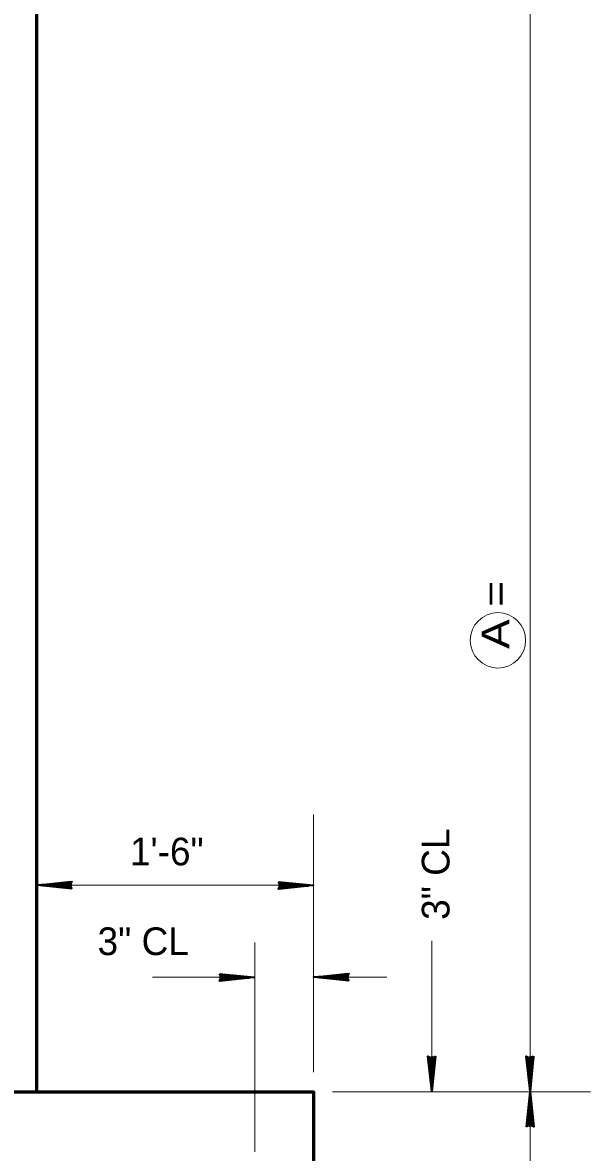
# Model space of a CAD drawing. Extents: x 6.34 to 9.53, y -1.46 to 0.53.
# Drawn here: x 7.298 to 7.4689, y -0.7412 to -0.4014 of the extents above; entities that cross this region are included whole.
import ezdxf

# ---------------------------------------------------------------- set-up
doc = ezdxf.new("R2010")
doc.units = 0
doc.header["$LTSCALE"] = 0.0033
doc.layers.add('1', color=7, linetype='Continuous', lineweight=40)

msp = doc.modelspace()

# ---------------------------------------------------------------- linework, layer by layer
at = {"layer": '1', "lineweight": 13}
for p, q in [((7.45075, -0.391417), (7.45075, -0.80625)), ((7.385583, -0.717), (7.385583, -0.639583)), ((7.30225, -0.660833), (7.385167, -0.660833)), ((7.367917, -0.741), (7.367917, -0.678083)), ((7.421167, -0.712917), (7.421167, -0.677583)), ((7.337083, -0.6885), (7.357917, -0.6885)), ((7.3955, -0.6885), (7.407667, -0.6885)), ((7.39125, -0.722917), (7.468917, -0.722917))]:
    msp.add_line(p, q, dxfattribs=at)
at = {"layer": '1', "lineweight": 35}
for p, q in [((7.312833, -0.660833), (7.30225, -0.660833)), ((7.312583, -0.661667), (7.30475, -0.660667)), ((7.312583, -0.661667), (7.30475, -0.660833)), ((7.312583, -0.661833), (7.30475, -0.660917)), ((7.312583, -0.661833), (7.30475, -0.660917)), ((7.312583, -0.66175), (7.30475, -0.660917)), ((7.312583, -0.65975), (7.30525, -0.660583)), ((7.312583, -0.659917), (7.30525, -0.660667)), ((7.312583, -0.66), (7.30525, -0.660833)), ((7.312667, -0.660167), (7.305333, -0.660917)), ((7.375, -0.660833), (7.385583, -0.660833)), ((7.375167, -0.6615), (7.3825, -0.66075)), ((7.37525, -0.659833), (7.383083, -0.66075)), ((7.37525, -0.659833), (7.383083, -0.66075)), ((7.37525, -0.659917), (7.383083, -0.66075)), ((7.37525, -0.66), (7.383083, -0.660833)), ((7.37525, -0.66), (7.383083, -0.661)), ((7.37525, -0.661667), (7.382583, -0.660833)), ((7.37525, -0.66175), (7.382583, -0.661)), ((7.37525, -0.661917), (7.382583, -0.661083)), ((7.35725, -0.6885), (7.367833, -0.6885)), ((7.357417, -0.689167), (7.36475, -0.688417)), ((7.3575, -0.6875), (7.365333, -0.688417)), ((7.3575, -0.6875), (7.365333, -0.688417)), ((7.3575, -0.687583), (7.365333, -0.688417)), ((7.3575, -0.687667), (7.365333, -0.6885)), ((7.3575, -0.687667), (7.365333, -0.688667)), ((7.3575, -0.689333), (7.364833, -0.6885)), ((7.3575, -0.689417), (7.364833, -0.688667)), ((7.3575, -0.689583), (7.364833, -0.68875)), ((7.396167, -0.6885), (7.385583, -0.6885)), ((7.395917, -0.689333), (7.388083, -0.688333)), ((7.395917, -0.689333), (7.388083, -0.6885)), ((7.395917, -0.6895), (7.388083, -0.688583)), ((7.395917, -0.6895), (7.388083, -0.688583)), ((7.395917, -0.689417), (7.388083, -0.688583)), ((7.395917, -0.687417), (7.388583, -0.68825)), ((7.395917, -0.687583), (7.388583, -0.688333)), ((7.395917, -0.687667), (7.388583, -0.6885)), ((7.396, -0.687833), (7.388667, -0.688583)), ((7.420083, -0.7125), (7.420917, -0.719833)), ((7.42025, -0.7125), (7.421, -0.719833)), ((7.420333, -0.7125), (7.421167, -0.719833)), ((7.4205, -0.712417), (7.42125, -0.71975)), ((7.422, -0.7125), (7.421, -0.720333)), ((7.421167, -0.71225), (7.421167, -0.722833)), ((7.422, -0.7125), (7.421167, -0.720333)), ((7.422167, -0.7125), (7.42125, -0.720333)), ((7.422167, -0.7125), (7.42125, -0.720333)), ((7.422083, -0.7125), (7.42125, -0.720333)), ((7.449667, -0.7125), (7.4505, -0.719833)), ((7.449833, -0.7125), (7.450583, -0.719833)), ((7.449917, -0.7125), (7.45075, -0.719833)), ((7.450083, -0.712417), (7.450833, -0.71975)), ((7.451583, -0.7125), (7.450583, -0.720333)), ((7.45075, -0.71225), (7.45075, -0.722833)), ((7.451583, -0.7125), (7.45075, -0.720333)), ((7.45175, -0.7125), (7.450833, -0.720333)), ((7.45175, -0.7125), (7.450833, -0.720333)), ((7.451667, -0.7125), (7.450833, -0.720333)), ((7.45075, -0.7335), (7.45075, -0.722917)), ((7.44975, -0.73325), (7.450667, -0.725417)), ((7.44975, -0.73325), (7.450667, -0.725417)), ((7.449833, -0.73325), (7.450667, -0.725417)), ((7.449917, -0.73325), (7.45075, -0.725417)), ((7.449917, -0.73325), (7.450917, -0.725417)), ((7.451417, -0.733333), (7.450667, -0.726)), ((7.451583, -0.73325), (7.45075, -0.725917)), ((7.451667, -0.73325), (7.450917, -0.725917)), ((7.451833, -0.73325), (7.451, -0.725917))]:
    msp.add_line(p, q, dxfattribs=at)
at = {"layer": '1', "lineweight": 60}
for points in [[(7.30225, -0.389583), (7.30225, -0.722917), (7.385583, -0.722917), (7.385583, -0.80625)], [(6.718917, -0.722917), (6.962083, -0.722917), (7.30225, -0.722917)]]:
    msp.add_lwpolyline(points, dxfattribs=at)
at = {"layer": '1', "lineweight": 35}
for points in [[(7.312833, -0.661917), (7.30225, -0.660833), (7.312833, -0.659667), (7.31225, -0.660833)], [(7.312083, -0.660917), (7.307417, -0.661), (7.307417, -0.660917), (7.308333, -0.660917), (7.312083, -0.661), (7.309083, -0.661083), (7.31225, -0.661167), (7.31, -0.66125), (7.31225, -0.661333), (7.30875, -0.661083), (7.304083, -0.660917), (7.305, -0.660667), (7.30375, -0.660667), (7.312083, -0.660667), (7.309667, -0.6605), (7.31225, -0.6605), (7.306917, -0.660917), (7.31225, -0.66025)], [(7.375, -0.65975), (7.385583, -0.660833), (7.375, -0.662), (7.375583, -0.660833)], [(7.37575, -0.66075), (7.380417, -0.660667), (7.380417, -0.66075), (7.3795, -0.66075), (7.37575, -0.660667), (7.37875, -0.660583), (7.375583, -0.6605), (7.377833, -0.660417), (7.375583, -0.660333), (7.379083, -0.660583), (7.38375, -0.66075), (7.382833, -0.661), (7.384083, -0.661), (7.37575, -0.661), (7.378167, -0.661167), (7.375583, -0.661167), (7.380917, -0.66075), (7.375583, -0.661417)], [(7.35725, -0.687417), (7.367833, -0.6885), (7.35725, -0.689667), (7.357833, -0.6885)], [(7.358, -0.688417), (7.362667, -0.688333), (7.362667, -0.688417), (7.36175, -0.688417), (7.358, -0.688333), (7.361, -0.68825), (7.357833, -0.688167), (7.360083, -0.688083), (7.357833, -0.688), (7.361333, -0.68825), (7.366, -0.688417), (7.365083, -0.688667), (7.366333, -0.688667), (7.358, -0.688667), (7.360417, -0.688833), (7.357833, -0.688833), (7.363167, -0.688417), (7.357833, -0.689083)], [(7.396167, -0.689583), (7.385583, -0.6885), (7.396167, -0.687333), (7.395583, -0.6885)], [(7.395417, -0.688583), (7.39075, -0.688667), (7.39075, -0.688583), (7.391667, -0.688583), (7.395417, -0.688667), (7.392417, -0.68875), (7.395583, -0.688833), (7.393333, -0.688917), (7.395583, -0.689), (7.392083, -0.68875), (7.387417, -0.688583), (7.388333, -0.688333), (7.387083, -0.688333), (7.395417, -0.688333), (7.393, -0.688167), (7.395583, -0.688167), (7.39025, -0.688583), (7.395583, -0.687917)], [(7.42225, -0.71225), (7.421167, -0.722833), (7.42, -0.71225), (7.421167, -0.712833)], [(7.42125, -0.713), (7.421333, -0.717667), (7.42125, -0.717667), (7.42125, -0.71675), (7.421333, -0.713), (7.421417, -0.716), (7.4215, -0.712833), (7.421583, -0.715083), (7.421667, -0.712833), (7.421417, -0.716333), (7.42125, -0.721), (7.421, -0.720083), (7.421, -0.721333), (7.421, -0.713), (7.420833, -0.715417), (7.420833, -0.712833), (7.42125, -0.718167), (7.420583, -0.712833)], [(7.451833, -0.71225), (7.45075, -0.722833), (7.449583, -0.71225), (7.45075, -0.712833)], [(7.450833, -0.713), (7.450917, -0.717667), (7.450833, -0.717667), (7.450833, -0.71675), (7.450917, -0.713), (7.451, -0.716), (7.451083, -0.712833), (7.451167, -0.715083), (7.45125, -0.712833), (7.451, -0.716333), (7.450833, -0.721), (7.450583, -0.720083), (7.450583, -0.721333), (7.450583, -0.713), (7.450417, -0.715417), (7.450417, -0.712833), (7.450833, -0.718167), (7.450167, -0.712833)], [(7.449667, -0.7335), (7.45075, -0.722917), (7.451917, -0.7335), (7.45075, -0.732917)], [(7.450667, -0.73275), (7.450583, -0.728083), (7.450667, -0.728083), (7.450667, -0.729), (7.450583, -0.73275), (7.4505, -0.72975), (7.450417, -0.732917), (7.450333, -0.730667), (7.45025, -0.732917), (7.4505, -0.729417), (7.450667, -0.72475), (7.450917, -0.725667), (7.450917, -0.724417), (7.450917, -0.73275), (7.451083, -0.730333), (7.451083, -0.732917), (7.450667, -0.727583), (7.451333, -0.732917)]]:
    msp.add_lwpolyline(points, close=True, dxfattribs=at)
for points in [[(7.312083, -0.660917), (7.3125, -0.661667), (7.31225, -0.661417), (7.312083, -0.661083), (7.311833, -0.661167), (7.312, -0.6615), (7.312167, -0.66075), (7.312333, -0.66025), (7.312583, -0.659833)], [(7.37575, -0.66075), (7.375333, -0.66), (7.375583, -0.66025), (7.37575, -0.660583), (7.376, -0.6605), (7.375833, -0.660167), (7.375667, -0.660917), (7.3755, -0.661417), (7.37525, -0.661833)], [(7.358, -0.688417), (7.357583, -0.687667), (7.357833, -0.687917), (7.358, -0.68825), (7.35825, -0.688167), (7.358083, -0.687833), (7.357917, -0.688583), (7.35775, -0.689083), (7.3575, -0.6895)], [(7.395417, -0.688583), (7.395833, -0.689333), (7.395583, -0.689083), (7.395417, -0.68875), (7.395167, -0.688833), (7.395333, -0.689167), (7.3955, -0.688417), (7.395667, -0.687917), (7.395917, -0.6875)], [(7.42125, -0.713), (7.422, -0.712583), (7.42175, -0.712833), (7.421417, -0.713), (7.4215, -0.71325), (7.421833, -0.713083), (7.421083, -0.712917), (7.420583, -0.71275), (7.420167, -0.7125)], [(7.450833, -0.713), (7.451583, -0.712583), (7.451333, -0.712833), (7.451, -0.713), (7.451083, -0.71325), (7.451417, -0.713083), (7.450667, -0.712917), (7.450167, -0.71275), (7.44975, -0.7125)], [(7.450667, -0.73275), (7.449917, -0.733167), (7.450167, -0.732917), (7.4505, -0.73275), (7.450417, -0.7325), (7.450083, -0.732667), (7.450833, -0.732833), (7.451333, -0.733), (7.45175, -0.73325)]]:
    msp.add_lwpolyline(points, dxfattribs=at)
at = {"layer": '1', "lineweight": 13}
msp.add_circle((7.441083, -0.587167), 0.008333, dxfattribs=at)

# ---------------------------------------------------------------- texts
at = {"layer": '1', "width": 1.2}
msp.add_text('A =      ', height=0.008334, rotation=90, dxfattribs=at).set_placement((7.4445, -0.58975))
at = {"layer": '1'}
msp.add_text('3" CL', height=0.008334, rotation=90, dxfattribs=at).set_placement((7.4265, -0.67125))
for s, p in [('1\'-6"', (7.330333, -0.654833)), ('3" CL', (7.320583, -0.681833))]:
    msp.add_text(s, height=0.008334, dxfattribs=at).set_placement(p)

doc.saveas('drawing.dxf')
